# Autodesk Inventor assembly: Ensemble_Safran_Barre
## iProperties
Shininess: 64.0
Length Units: 11269
Angle Units: 11279
Time Units: 11290
Mass Units: 11283
Length Display Precision: 3
Angle Display Precision: 2
Compacted: True
Created: 2004-05
Part Number: Ensemble_Safran_Barre
Document SubType Name: Assembly
Designer: David
Density: 0.0
Volumn: 0.0
Area: 0.0
PropertySet Name: Model Information
Control State: 0
Master: False
Checked Out: False
Author: David
